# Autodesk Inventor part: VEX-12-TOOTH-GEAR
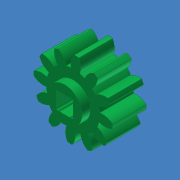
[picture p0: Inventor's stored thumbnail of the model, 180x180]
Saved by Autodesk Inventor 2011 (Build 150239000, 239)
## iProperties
Created: 2007-08
Part Number: VEX-12-TOOTH-GEAR
Material: ABS Plastic
Document SubType Name: Modeling
Density: 1.06 g/cm^3
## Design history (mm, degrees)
feature "Base1"
body "Solid1"
